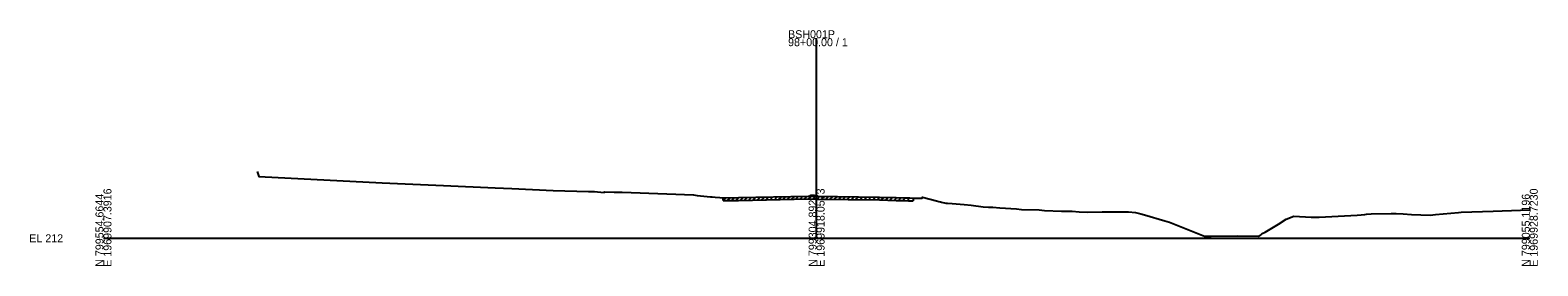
# Model space of a CAD drawing. Extents: x 1979833 to 1982361, y 790388 to 810009.
# Drawn here: x 1981583 to 1982111, y 799388 to 799471 of the extents above; entities that cross this region are included whole.
import ezdxf

# ---------------------------------------------------------------- set-up
doc = ezdxf.new("R2010")
doc.units = 0
for name, color, linetype in [('Default', 7, 'Continuous'), ('RD_GPK_XS_Cell', 7, 'Continuous'), ('RD_XS_ExGround', 7, 'Continuous'), ('RD_XS_ExPaveRet', 7, 'Continuous')]:
    doc.layers.add(name, color=color, linetype=linetype)

msp = doc.modelspace()

# ---------------------------------------------------------------- linework, layer by layer
at = {"layer": 'RD_GPK_XS_Cell'}
for p, q in [((1981858.57, 799397.73), (1981858.57, 799467.95)), ((1981608.57, 799397.73), (1981858.57, 799397.73)), ((1981858.57, 799397.73), (1982108.57, 799397.73))]:
    msp.add_line(p, q, dxfattribs=at)
at = {"layer": 'RD_XS_ExGround'}
msp.add_lwpolyline([(1981662.44, 799421.14), (1981663.06, 799419.43), (1981706.31, 799417.24), (1981727.83, 799416.26), (1981745.86, 799415.48), (1981751.72, 799415.22), (1981766.24, 799414.55), (1981778.59, 799414.1), (1981779.01, 799414.13), (1981780.7, 799414.15), (1981781.81, 799414.03), (1981784.06, 799413.85), (1981784.16, 799414.04), (1981787.64, 799413.94), (1981790.41, 799413.89), (1981806.01, 799413.32), (1981815.41, 799412.95), (1981816.72, 799412.75), (1981821.4, 799412.3), (1981822, 799412.26), (1981822.98, 799412.2), (1981824.67, 799412.07), (1981825.76, 799411.98), (1981826.31, 799411.97), (1981826.75, 799411.95), (1981831.24, 799412.02), (1981855.65, 799412.53), (1981858.57, 799412.49), (1981880.62, 799412.18), (1981886.46, 799412.03), (1981889.05, 799411.98), (1981890.78, 799411.9), (1981891.3, 799411.88), (1981892.47, 799411.85), (1981893.12, 799411.82), (1981895.61, 799411.81), (1981895.69, 799412.13), (1981900.55, 799410.85), (1981901.37, 799410.63), (1981901.95, 799410.49), (1981902.3, 799410.43), (1981903.85, 799410.07), (1981904.48, 799410.02), (1981906.13, 799409.97), (1981910.27, 799409.58), (1981912.75, 799409.33), (1981916.91, 799408.77), (1981918.85, 799408.64), (1981920.39, 799408.59), (1981922.83, 799408.46), (1981928.64, 799408.1), (1981930.35, 799407.87), (1981936.56, 799407.72), (1981938.51, 799407.49), (1981944.39, 799407.27), (1981948.14, 799407.2), (1981950.57, 799406.96), (1981953.65, 799406.9), (1981958.63, 799407.03), (1981961.56, 799407.03), (1981967.11, 799406.99), (1981967.9, 799406.98), (1981970.31, 799406.8), (1981972.24, 799406.31), (1981973.47, 799405.92), (1981980.67, 799403.86), (1981982.26, 799403.33), (1981994.53, 799398.48), (1981995.54, 799398.5), (1981996.84, 799398.51), (1982006.05, 799398.62), (1982013.43, 799398.52), (1982014.31, 799398.95), (1982014.73, 799399.36), (1982015.84, 799399.89), (1982020.44, 799402.71), (1982023.14, 799404.44), (1982025.91, 799405.46), (1982031.93, 799405.19), (1982034.72, 799405.1), (1982048.11, 799405.87), (1982049.42, 799405.96), (1982050.78, 799406.13), (1982051.34, 799406.2), (1982052.96, 799406.33), (1982059.98, 799406.39), (1982061.72, 799406.41), (1982064.15, 799406.29), (1982067.1, 799406.13), (1982073.65, 799405.88), (1982075.53, 799406.02), (1982083.55, 799406.8), (1982084.53, 799406.84), (1982095.74, 799407.21), (1982105.28, 799407.56), (1982108.57, 799407.7)], dxfattribs=at)
at = {"layer": 'RD_XS_ExPaveRet'}
for p, q in [((1981825.76, 799410.98), (1981825.76, 799411.98)), ((1981825.76, 799410.98), (1981826.73, 799411.96)), ((1981825.76, 799410.98), (1981826.31, 799410.97)), ((1981826.31, 799410.97), (1981826.75, 799410.95)), ((1981826.75, 799410.95), (1981831.24, 799411.02)), ((1981827.26, 799410.96), (1981828.27, 799411.98)), ((1981828.76, 799410.98), (1981829.77, 799412)), ((1981830.26, 799411.01), (1981831.27, 799412.02)), ((1981831.24, 799411.02), (1981855.65, 799411.53)), ((1981831.76, 799411.03), (1981832.78, 799412.05)), ((1981833.26, 799411.06), (1981834.28, 799412.08)), ((1981834.76, 799411.09), (1981835.78, 799412.12)), ((1981836.26, 799411.13), (1981837.28, 799412.15)), ((1981837.76, 799411.16), (1981838.78, 799412.18)), ((1981839.26, 799411.19), (1981840.28, 799412.21)), ((1981840.76, 799411.22), (1981841.78, 799412.24)), ((1981842.26, 799411.25), (1981843.28, 799412.27)), ((1981843.76, 799411.28), (1981844.78, 799412.3)), ((1981845.26, 799411.31), (1981846.28, 799412.33)), ((1981846.76, 799411.34), (1981847.78, 799412.36)), ((1981848.26, 799411.37), (1981849.28, 799412.39)), ((1981849.76, 799411.4), (1981850.78, 799412.42)), ((1981851.26, 799411.43), (1981852.28, 799412.46)), ((1981852.76, 799411.47), (1981853.78, 799412.49)), ((1981854.26, 799411.5), (1981855.28, 799412.52)), ((1981855.65, 799411.53), (1981858.57, 799411.49)), ((1981855.76, 799411.52), (1981856.74, 799412.51)), ((1981857.26, 799411.5), (1981858.24, 799412.49)), ((1981858.57, 799411.49), (1981880.62, 799411.18)), ((1981858.76, 799411.48), (1981859.74, 799412.47)), ((1981860.26, 799411.46), (1981861.24, 799412.45)), ((1981861.76, 799411.44), (1981862.74, 799412.43)), ((1981863.26, 799411.42), (1981864.24, 799412.41)), ((1981864.76, 799411.4), (1981865.74, 799412.39)), ((1981866.26, 799411.38), (1981867.24, 799412.37)), ((1981867.76, 799411.36), (1981868.74, 799412.35)), ((1981869.26, 799411.34), (1981870.24, 799412.32)), ((1981870.76, 799411.32), (1981871.74, 799412.3)), ((1981872.26, 799411.3), (1981873.24, 799412.28)), ((1981873.76, 799411.28), (1981874.74, 799412.26)), ((1981875.26, 799411.26), (1981876.24, 799412.24)), ((1981876.76, 799411.24), (1981877.74, 799412.22)), ((1981878.26, 799411.21), (1981879.24, 799412.2)), ((1981879.76, 799411.19), (1981880.74, 799412.18)), ((1981880.62, 799411.18), (1981886.46, 799411.03)), ((1981881.26, 799411.17), (1981882.23, 799412.14)), ((1981882.76, 799411.12), (1981883.73, 799412.1)), ((1981884.26, 799411.08), (1981885.23, 799412.06)), ((1981885.76, 799411.04), (1981886.73, 799412.02)), ((1981886.46, 799411.03), (1981889.05, 799410.98)), ((1981887.26, 799411.01), (1981888.24, 799411.99)), ((1981888.76, 799410.98), (1981889.72, 799411.94)), ((1981889.05, 799410.98), (1981890.78, 799410.9)), ((1981890.26, 799410.92), (1981891.22, 799411.89)), ((1981890.78, 799410.9), (1981891.3, 799410.88)), ((1981891.3, 799410.88), (1981892.47, 799410.85)), ((1981892.47, 799411.85), (1981892.47, 799410.85))]:
    msp.add_line(p, q, dxfattribs=at)

# ---------------------------------------------------------------- texts
at = {"layer": 'Default'}
msp.add_text('-', height=0.0001, dxfattribs=at).set_placement((1981608.57, 799397.73))
at = {"layer": 'RD_GPK_XS_Cell'}
for s, p in [('BSH001P', (1981848.57, 799467.95)), ('98+00.00 / 1', (1981848.57, 799465.15)), ('EL 212', (1981582.57, 799396.33))]:
    msp.add_text(s, height=2.8, dxfattribs=at).set_placement(p)
for s, p in [('N 799554.6644', (1981608.57, 799387.73)), ('E 1969907.3916', (1981611.37, 799387.73)), ('N 799304.8920', (1981858.57, 799387.73)), ('E 1969918.0573', (1981861.37, 799387.73)), ('N 799055.1196', (1982108.57, 799387.73)), ('E 1969928.7230', (1982111.37, 799387.73))]:
    msp.add_text(s, height=2.8, rotation=90, dxfattribs=at).set_placement(p)

doc.saveas('drawing.dxf')
